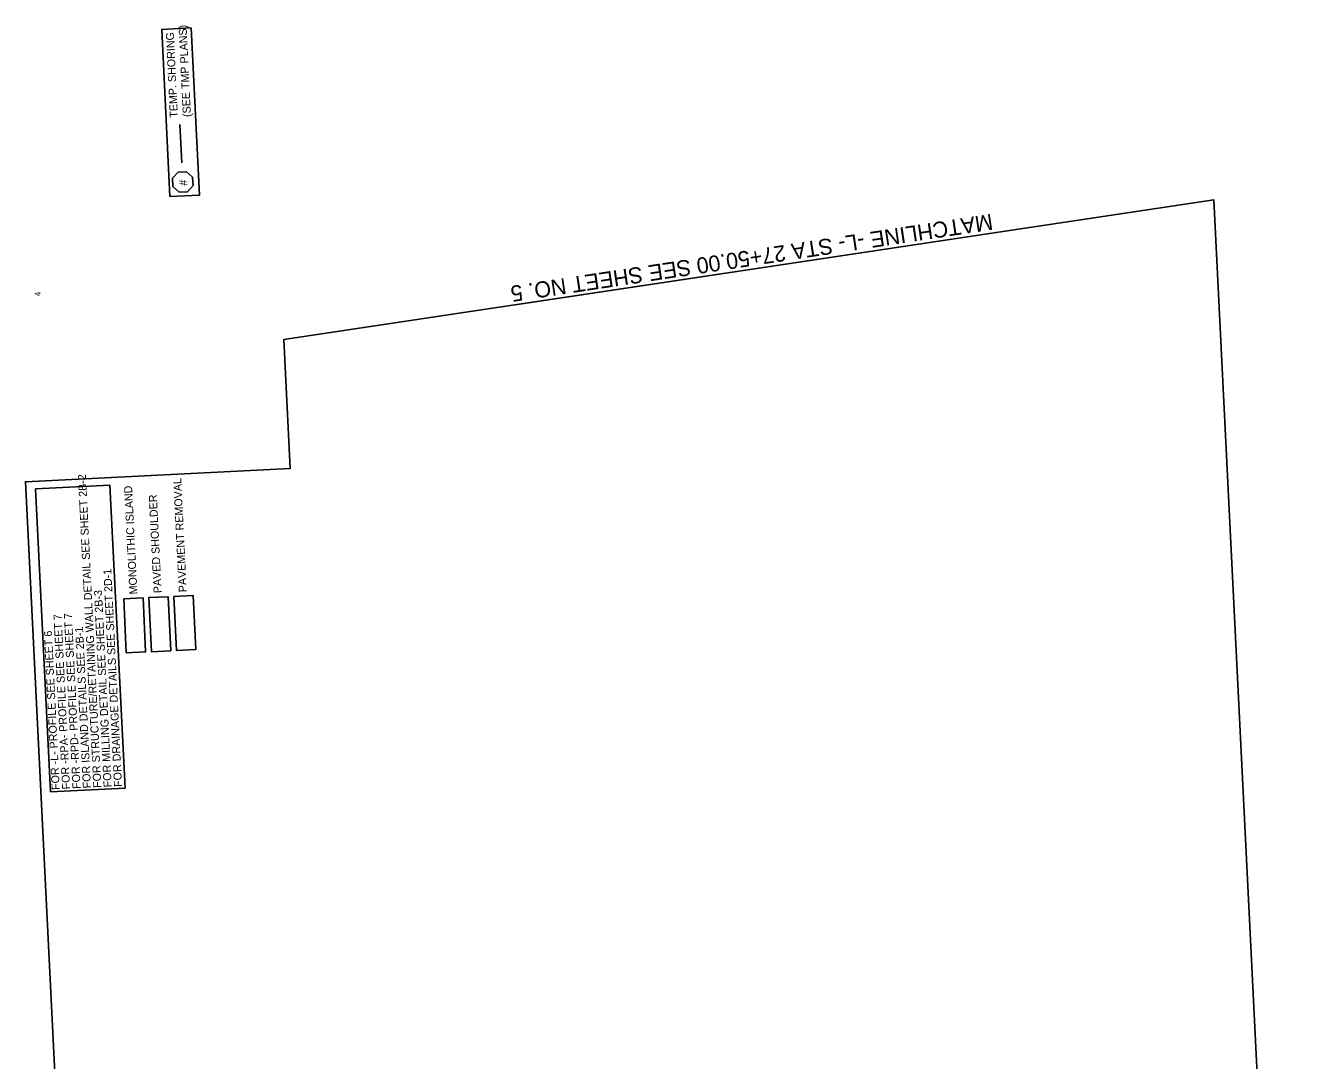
# Model space of a CAD drawing. Extents: x 1807150 to 1808331, y 913657 to 915467.
# Drawn here: x 1807218 to 1808331, y 914562 to 915467 of the extents above; entities that cross this region are included whole.
import ezdxf

# ---------------------------------------------------------------- set-up
doc = ezdxf.new("R2010")
doc.units = 0
for name, color, linetype in [('Exist Drainage Structure Drop Inlet CELL', 7, 'Continuous'), ('Exist Hydrographic Top of Bank', 7, 'Continuous'), ('Exist Plan Preparation Watershed Blue', 7, 'Continuous'), ('Old_Level_44', 7, 'Continuous'), ('Prop Boundary Buffer Zone 1', 7, 'Continuous'), ('Prop Drainage Structure Drop Inlet Grate 2 Narrow Slots and Flat Grates 840 29 TB CELL', 7, 'Continuous'), ('Prop Drainage Structure Plot Symbol 20 Scale', 7, 'Continuous'), ('Prop Drainage Structure Plot Symbol 50 Scale', 7, 'Continuous'), ('Scratch_Level_2', 7, 'Continuous'), ('Scratch_Level_3', 7, 'Continuous')]:
    doc.layers.add(name, color=color, linetype=linetype)

msp = doc.modelspace()

# ---------------------------------------------------------------- linework, layer by layer
at = {"layer": 'Exist Drainage Structure Drop Inlet CELL'}
msp.add_line((1807354.8, 915347.1), (1807353.1, 915380.7), dxfattribs=at)
at = {"layer": 'Exist Hydrographic Top of Bank'}
for points in [[(1807344.5, 915317.5), (1807337.3, 915463.7), (1807363, 915465), (1807370.3, 915318.7)], [(1807240.1, 914797.2), (1807227, 915061.9), (1807292.1, 915065.1), (1807305.3, 914800.4)]]:
    msp.add_lwpolyline(points, close=True, dxfattribs=at)
at = {"layer": 'Exist Plan Preparation Watershed Blue'}
msp.add_line((1808042, 915282.4), (1807646.4, 915222.9), dxfattribs=at)
at = {"layer": 'Prop Boundary Buffer Zone 1'}
for p, q in [((1807351.7, 915339), (1807346.9, 915333.6)), ((1807359, 915339.3), (1807351.7, 915339)), ((1807364.4, 915334.4), (1807359, 915339.3)), ((1807346.9, 915333.6), (1807347.2, 915326.3)), ((1807347.2, 915326.3), (1807352.6, 915321.4)), ((1807359.9, 915321.8), (1807364.7, 915327.2)), ((1807364.7, 915327.2), (1807364.4, 915334.4)), ((1807352.6, 915321.4), (1807359.9, 915321.8))]:
    msp.add_line(p, q, dxfattribs=at)
at = {"layer": 'Prop Drainage Structure Drop Inlet Grate 2 Narrow Slots and Flat Grates 840 29 TB CELL'}
for points in [[(1807347.9, 914968), (1807350.2, 914920.7), (1807367.1, 914921.6), (1807364.8, 914968.8)], [(1807304.1, 914965.8), (1807306.4, 914918.6), (1807323.3, 914919.4), (1807321, 914966.7)], [(1807326, 914966.9), (1807328.3, 914919.6), (1807345.2, 914920.5), (1807342.9, 914967.7)]]:
    msp.add_lwpolyline(points, close=True, dxfattribs=at)
msp.add_lwpolyline([(1807326, 914966.9), (1807328.3, 914919.6), (1807345.2, 914920.5), (1807342.9, 914967.7), (1807326, 914966.9)], dxfattribs=at)
at = {"layer": 'Prop Drainage Structure Plot Symbol 20 Scale'}
msp.add_lwpolyline([(1807304.1, 914965.8), (1807306.4, 914918.6), (1807323.3, 914919.4), (1807321, 914966.7), (1807304.1, 914965.8)], dxfattribs=at)
at = {"layer": 'Scratch_Level_2'}
msp.add_lwpolyline([(1807282.7, 913769.8), (1807380.3, 913774.7), (1807377.1, 913839), (1807613.9, 913850.7), (1807644.9, 913787.8), (1808331.4, 913821.9), (1808315.3, 914144.7), (1808045.3, 914131.3), (1808034.8, 914342.5), (1808304.9, 914355.9), (1808257.3, 915314.8), (1807444, 915192.5), (1807449.6, 915079.7), (1807218.2, 915068.2)], close=True, dxfattribs=at)
at = {"layer": 'Scratch_Level_3'}
msp.add_lwpolyline([(1807326, 914966.9), (1807328.3, 914919.6), (1807345.2, 914920.5), (1807342.9, 914967.7), (1807326, 914966.9)], dxfattribs=at)
msp.add_lwpolyline([(1807326, 914966.9), (1807328.3, 914919.6), (1807345.2, 914920.5), (1807342.9, 914967.7)], close=True, dxfattribs=at)

# ---------------------------------------------------------------- texts
at = {"layer": 'Old_Level_44'}
msp.add_text('4', height=5, rotation=92.8422, dxfattribs=at).set_placement((1807231.5, 915230.7))
at = {"layer": 'Prop Boundary Buffer Zone 1'}
for s, rotation, p in [('TEMP. SHORING', 92.7472, (1807351.5, 915386.7)), ('(SEE TMP PLANS)', 92.7472, (1807362.9, 915387.3)), ('#', 92.8422, (1807359.8, 915327.3)), ('FOR STRUCTURE/RETAINING WALL DETAIL SEE SHEET 2B-2', 92.8419, (1807284.6, 914800.7)), ('PAVEMENT REMOVAL', 92.8422, (1807359.3, 914971.8)), ('MONOLITHIC ISLAND', 92.8422, (1807316.1, 914969.9)), ('PAVED SHOULDER', 92.8422, (1807337.3, 914971)), ('FOR DRAINAGE DETAILS SEE SHEET 2D-1', 92.8419, (1807302.7, 914801.6)), ('FOR MILLING DETAIL SEE SHEET 2B-3', 92.8419, (1807293.6, 914801.2)), ('FOR -RPA- PROFILE SEE SHEET 7', 92.8419, (1807257.3, 914799.4)), ('FOR -RPD- PROFILE SEE SHEET 7', 92.8419, (1807266.4, 914799.8)), ('FOR -L- PROFILE SEE SHEET 6', 92.8419, (1807248.2, 914798.9)), ('FOR ISLAND DETAILS SEE 2B-1', 92.8419, (1807275.5, 914800.3))]:
    msp.add_text(s, height=7, rotation=rotation, dxfattribs=at).set_placement(p)
at = {"layer": 'Prop Drainage Structure Plot Symbol 50 Scale'}
msp.add_text('MATCHLINE -L- STA 27+50.00 SEE SHEET NO. 5', height=14, rotation=188.5557, dxfattribs=at).set_placement((1808062.9, 915302.6))

doc.saveas('drawing.dxf')
